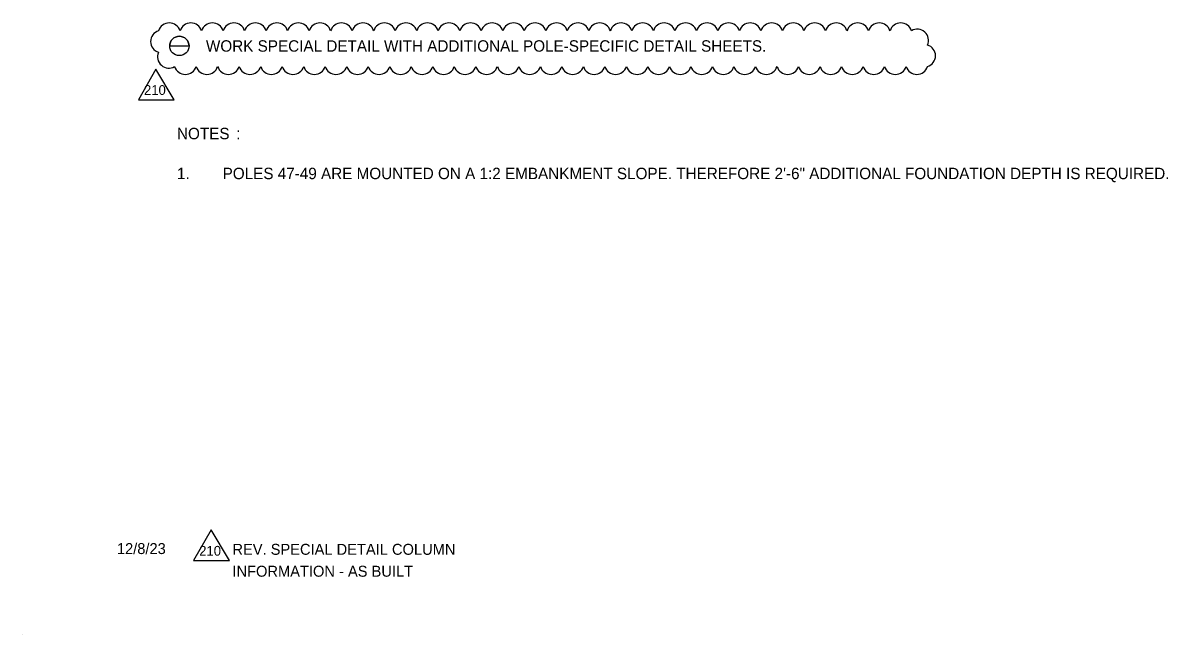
# Model space of a CAD drawing. Extents: x -816.7 to -800.7, y -2197.9 to -2187.9.
# Drawn here: x -816.67 to -809.64, y -2197.9 to -2194.15 of the extents above; entities that cross this region are included whole.
import ezdxf

# ---------------------------------------------------------------- set-up
doc = ezdxf.new("R2010")
doc.units = 0
for name, color, linetype in [('AdhocPoint_dp', 7, 'Continuous'), ('ScratchEle_dp', 7, 'Continuous'), ('TextLabel', 7, 'Continuous'), ('TextMinor', 7, 'Continuous')]:
    doc.layers.add(name, color=color, linetype=linetype)

msp = doc.modelspace()

# ---------------------------------------------------------------- linework, layer by layer
at = {"layer": 'AdhocPoint_dp'}
msp.add_line((-816.6686, -2197.8985), (-816.6686, -2197.8985), dxfattribs=at)
at = {"layer": 'ScratchEle_dp'}
for points in [[(-815.8525, -2194.4323), (-815.9603, -2194.6204), (-815.7396, -2194.6204)], [(-815.5137, -2197.2596), (-815.6215, -2197.4477), (-815.4008, -2197.4477)]]:
    msp.add_lwpolyline(points, close=True, dxfattribs=at)
for centre, radius, start, end in [((-815.7704, -2194.2175), 0.0692, 17.5, 162.5), ((-815.6384, -2194.2175), 0.0692, 17.5, 162.5), ((-815.5064, -2194.2175), 0.0692, 17.5, 162.5), ((-815.3744, -2194.2175), 0.0692, 17.5, 162.5), ((-815.2425, -2194.2175), 0.0692, 17.5, 162.5), ((-815.1105, -2194.2175), 0.0692, 17.5, 162.5), ((-814.9785, -2194.2175), 0.0692, 17.5, 162.5), ((-814.8465, -2194.2175), 0.0692, 17.5, 162.5), ((-814.7145, -2194.2175), 0.0692, 17.5, 162.5), ((-814.5826, -2194.2175), 0.0692, 17.5, 162.5), ((-814.4506, -2194.2175), 0.0692, 17.5, 162.5), ((-814.3186, -2194.2175), 0.0692, 17.5, 162.5), ((-814.1866, -2194.2175), 0.0692, 17.5, 162.5), ((-814.0546, -2194.2175), 0.0692, 17.5, 162.5), ((-813.9226, -2194.2175), 0.0692, 17.5, 162.5), ((-813.7907, -2194.2175), 0.0692, 17.5, 162.5), ((-813.6587, -2194.2175), 0.0692, 17.5, 162.5), ((-813.5267, -2194.2175), 0.0692, 17.5, 162.5), ((-813.3947, -2194.2175), 0.0692, 17.5, 162.5), ((-813.2627, -2194.2175), 0.0692, 17.5, 162.5), ((-813.1307, -2194.2175), 0.0692, 17.5, 162.5), ((-812.9988, -2194.2175), 0.0692, 17.5, 162.5), ((-812.8668, -2194.2175), 0.0692, 17.5, 162.5), ((-812.7348, -2194.2175), 0.0692, 17.5, 162.5), ((-812.6028, -2194.2175), 0.0692, 17.5, 162.5), ((-812.4708, -2194.2175), 0.0692, 17.5, 162.5), ((-812.3388, -2194.2175), 0.0692, 17.5, 162.5), ((-812.2069, -2194.2175), 0.0692, 17.5, 162.5), ((-812.0749, -2194.2175), 0.0692, 17.5, 162.5), ((-811.9429, -2194.2175), 0.0692, 17.5, 162.5), ((-811.8109, -2194.2175), 0.0692, 17.5, 162.5), ((-811.6789, -2194.2175), 0.0692, 17.5, 162.5), ((-811.5469, -2194.2175), 0.0692, 17.5, 162.5), ((-811.415, -2194.2175), 0.0692, 17.5, 162.5), ((-811.283, -2194.2175), 0.0692, 17.5, 162.5), ((-811.1815, -2194.256), 0.0691, 335.91104, 120.91104), ((-815.8156, -2194.2627), 0.0692, 107.5, 252.5), ((-815.7733, -2194.3569), 0.0691, 155.91104, 300.91104), ((-811.1391, -2194.3502), 0.0692, 287.5, 72.5), ((-815.6718, -2194.3954), 0.0692, 197.5, 342.5), ((-815.5398, -2194.3954), 0.0692, 197.5, 342.5), ((-815.4078, -2194.3954), 0.0692, 197.5, 342.5), ((-815.2758, -2194.3954), 0.0692, 197.5, 342.5), ((-815.1438, -2194.3954), 0.0692, 197.5, 342.5), ((-815.0118, -2194.3954), 0.0692, 197.5, 342.5), ((-814.8799, -2194.3954), 0.0692, 197.5, 342.5), ((-814.7479, -2194.3954), 0.0692, 197.5, 342.5), ((-814.6159, -2194.3954), 0.0692, 197.5, 342.5), ((-814.4839, -2194.3954), 0.0692, 197.5, 342.5), ((-814.3519, -2194.3954), 0.0692, 197.5, 342.5), ((-814.2199, -2194.3954), 0.0692, 197.5, 342.5), ((-814.088, -2194.3954), 0.0692, 197.5, 342.5), ((-813.956, -2194.3954), 0.0692, 197.5, 342.5), ((-813.824, -2194.3954), 0.0692, 197.5, 342.5), ((-813.692, -2194.3954), 0.0692, 197.5, 342.5), ((-813.56, -2194.3954), 0.0692, 197.5, 342.5), ((-813.428, -2194.3954), 0.0692, 197.5, 342.5), ((-813.2961, -2194.3954), 0.0692, 197.5, 342.5), ((-813.1641, -2194.3954), 0.0692, 197.5, 342.5), ((-813.0321, -2194.3954), 0.0692, 197.5, 342.5), ((-812.9001, -2194.3954), 0.0692, 197.5, 342.5), ((-812.7681, -2194.3954), 0.0692, 197.5, 342.5), ((-812.6361, -2194.3954), 0.0692, 197.5, 342.5), ((-812.5042, -2194.3954), 0.0692, 197.5, 342.5), ((-812.3722, -2194.3954), 0.0692, 197.5, 342.5), ((-812.2402, -2194.3954), 0.0692, 197.5, 342.5), ((-812.1082, -2194.3954), 0.0692, 197.5, 342.5), ((-811.9762, -2194.3954), 0.0692, 197.5, 342.5), ((-811.8442, -2194.3954), 0.0692, 197.5, 342.5), ((-811.7123, -2194.3954), 0.0692, 197.5, 342.5), ((-811.5803, -2194.3954), 0.0692, 197.5, 342.5), ((-811.4483, -2194.3954), 0.0692, 197.5, 342.5), ((-811.3163, -2194.3954), 0.0692, 197.5, 342.5), ((-811.1843, -2194.3954), 0.0692, 197.5, 342.5)]:
    msp.add_arc(centre, radius, start, end, dxfattribs=at)
at = {"layer": 'TextLabel'}
msp.add_line((-815.7681, -2194.2899), (-815.6496, -2194.2899), dxfattribs=at)
msp.add_line((-815.7681, -2194.2899), (-815.6496, -2194.2899), dxfattribs=at)
msp.add_circle((-815.7089, -2194.2899), 0.0593, dxfattribs=at)
msp.add_arc((-815.7089, -2194.2899), 0.0593, 0, 180, dxfattribs=at)

# ---------------------------------------------------------------- texts
at = {"layer": 'ScratchEle_dp'}
for p in [(-815.9258, -2194.5903), (-815.587, -2197.4175)]:
    msp.add_text('210', height=0.05998, rotation=0, dxfattribs=at).set_placement(p)
at = {"layer": 'TextLabel'}
for s, p in [('WORK SPECIAL DETAIL WITH ADDITIONAL POLE-SPECIFIC DETAIL SHEETS.', (-815.5457, -2194.3249)), ('NOTES', (-815.7233, -2194.8621)), (':', (-815.3599, -2194.8621)), ('1.', (-815.7233, -2195.1071)), ('POLES 47-49 ARE MOUNTED ON A 1:2 EMBANKMENT SLOPE. THEREFORE 2\'-6" ADDITIONAL FOUNDATION DEPTH IS REQUIRED.', (-815.4433, -2195.1071))]:
    msp.add_text(s, height=0.07, dxfattribs=at).set_placement(p)
at = {"layer": 'TextMinor'}
for s, p in [('12/8/23', (-816.0919, -2197.4075)), ('REV. SPECIAL DETAIL COLUMN ', (-815.3832, -2197.412)), ('INFORMATION - AS BUILT', (-815.3832, -2197.5464))]:
    msp.add_text(s, height=0.0672, rotation=360, dxfattribs=at).set_placement(p)

doc.saveas('drawing.dxf')
